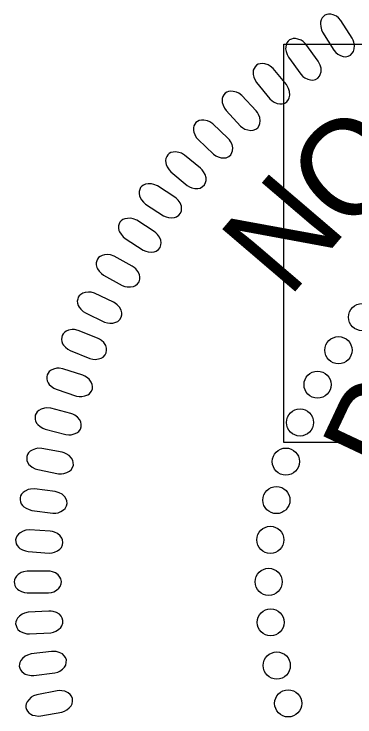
# Model space of a CAD drawing. Extents: x 505602 to 507286, y 483109 to 489436.
# Drawn here: x 507079.65 to 507099.79, y 484086.3 to 484127.78 of the extents above; entities that cross this region are included whole.
import ezdxf

# ---------------------------------------------------------------- set-up
doc = ezdxf.new("R2010")
doc.units = 0
doc.layers.add('Sheet PE Seal Cell', color=7, linetype='Continuous')
doc.layers.add('Sheet Sticker Incomplete CELL', color=7, linetype='Continuous')

msp = doc.modelspace()

# ---------------------------------------------------------------- linework, layer by layer
at = {"layer": 'Sheet PE Seal Cell'}
for points in [[(507099.622, 484126.354), (507098.965, 484127.39), (507098.816, 484127.556), (507098.698, 484127.645), (507098.512, 484127.729), (507098.371, 484127.769), (507098.234, 484127.776), (507098.124, 484127.754), (507098.019, 484127.711), (507097.934, 484127.634), (507097.85, 484127.545), (507097.793, 484127.438), (507097.758, 484127.298), (507097.751, 484127.198), (507097.774, 484127.036), (507097.82, 484126.852), (507097.886, 484126.705), (507098.553, 484125.64), (507098.662, 484125.509), (507098.775, 484125.415), (507098.937, 484125.329), (507099.106, 484125.271), (507099.23, 484125.255), (507099.395, 484125.289), (507099.532, 484125.352), (507099.637, 484125.466), (507099.699, 484125.564), (507099.753, 484125.716), (507099.763, 484125.924), (507099.723, 484126.111), (507099.679, 484126.236)], [(507097.622, 484124.999), (507096.901, 484125.992), (507096.742, 484126.148), (507096.618, 484126.23), (507096.427, 484126.302), (507096.284, 484126.333), (507096.147, 484126.331), (507096.038, 484126.303), (507095.936, 484126.253), (507095.857, 484126.171), (507095.778, 484126.076), (507095.728, 484125.967), (507095.702, 484125.824), (507095.7, 484125.725), (507095.734, 484125.563), (507095.791, 484125.383), (507095.867, 484125.241), (507096.599, 484124.22), (507096.717, 484124.096), (507096.835, 484124.009), (507097.001, 484123.932), (507097.174, 484123.886), (507097.3, 484123.878), (507097.462, 484123.922), (507097.594, 484123.994), (507097.692, 484124.114), (507097.747, 484124.215), (507097.792, 484124.371), (507097.789, 484124.579), (507097.738, 484124.763), (507097.686, 484124.886)], [(507095.741, 484123.61), (507094.959, 484124.556), (507094.791, 484124.701), (507094.662, 484124.776), (507094.468, 484124.835), (507094.323, 484124.858), (507094.185, 484124.848), (507094.08, 484124.811), (507093.98, 484124.755), (507093.906, 484124.668), (507093.834, 484124.569), (507093.79, 484124.457), (507093.774, 484124.312), (507093.778, 484124.213), (507093.822, 484124.055), (507093.89, 484123.878), (507093.975, 484123.741), (507094.769, 484122.768), (507094.895, 484122.651), (507095.018, 484122.573), (507095.189, 484122.507), (507095.364, 484122.471), (507095.49, 484122.471), (507095.649, 484122.525), (507095.777, 484122.605), (507095.867, 484122.731), (507095.916, 484122.836), (507095.95, 484122.994), (507095.934, 484123.2), (507095.872, 484123.382), (507095.812, 484123.501)], [(507093.954, 484122.071), (507093.114, 484122.966), (507092.937, 484123.101), (507092.803, 484123.167), (507092.605, 484123.214), (507092.46, 484123.227), (507092.323, 484123.209), (507092.219, 484123.166), (507092.124, 484123.104), (507092.056, 484123.012), (507091.989, 484122.908), (507091.954, 484122.794), (507091.946, 484122.649), (507091.956, 484122.55), (507092.01, 484122.395), (507092.089, 484122.223), (507092.181, 484122.092), (507093.037, 484121.17), (507093.169, 484121.061), (507093.297, 484120.991), (507093.472, 484120.936), (507093.65, 484120.91), (507093.775, 484120.918), (507093.93, 484120.982), (507094.053, 484121.071), (507094.134, 484121.202), (507094.177, 484121.31), (507094.201, 484121.469), (507094.173, 484121.674), (507094.098, 484121.852), (507094.032, 484121.967)], [(507092.291, 484120.462), (507091.398, 484121.302), (507091.212, 484121.425), (507091.074, 484121.483), (507090.874, 484121.517), (507090.728, 484121.522), (507090.592, 484121.494), (507090.492, 484121.445), (507090.401, 484121.377), (507090.339, 484121.282), (507090.278, 484121.174), (507090.25, 484121.057), (507090.251, 484120.913), (507090.268, 484120.814), (507090.331, 484120.662), (507090.421, 484120.496), (507090.522, 484120.37), (507091.433, 484119.504), (507091.571, 484119.405), (507091.704, 484119.342), (507091.882, 484119.298), (507092.06, 484119.284), (507092.185, 484119.3), (507092.336, 484119.374), (507092.453, 484119.469), (507092.526, 484119.605), (507092.561, 484119.715), (507092.576, 484119.877), (507092.534, 484120.08), (507092.45, 484120.252), (507092.376, 484120.362)], [(507090.678, 484118.675), (507089.733, 484119.458), (507089.54, 484119.568), (507089.399, 484119.617), (507089.197, 484119.639), (507089.051, 484119.634), (507088.918, 484119.599), (507088.821, 484119.544), (507088.734, 484119.47), (507088.677, 484119.371), (507088.625, 484119.259), (507088.603, 484119.141), (507088.614, 484118.997), (507088.637, 484118.9), (507088.709, 484118.752), (507088.81, 484118.591), (507088.918, 484118.473), (507089.881, 484117.666), (507090.026, 484117.575), (507090.162, 484117.521), (507090.343, 484117.488), (507090.521, 484117.485), (507090.645, 484117.51), (507090.791, 484117.592), (507090.901, 484117.694), (507090.966, 484117.835), (507090.995, 484117.947), (507090.999, 484118.109), (507090.945, 484118.309), (507090.849, 484118.475), (507090.768, 484118.581)], [(507089.153, 484116.973), (507088.123, 484117.639), (507087.918, 484117.726), (507087.773, 484117.758), (507087.57, 484117.756), (507087.425, 484117.734), (507087.297, 484117.683), (507087.207, 484117.617), (507087.129, 484117.533), (507087.085, 484117.429), (507087.046, 484117.312), (507087.038, 484117.192), (507087.066, 484117.05), (507087.1, 484116.956), (507087.189, 484116.818), (507087.308, 484116.67), (507087.429, 484116.565), (507088.481, 484115.877), (507088.635, 484115.803), (507088.777, 484115.766), (507088.96, 484115.754), (507089.138, 484115.773), (507089.258, 484115.812), (507089.393, 484115.911), (507089.491, 484116.025), (507089.538, 484116.172), (507089.553, 484116.287), (507089.539, 484116.448), (507089.461, 484116.64), (507089.347, 484116.795), (507089.254, 484116.89)], [(507087.939, 484114.95), (507086.904, 484115.608), (507086.699, 484115.694), (507086.553, 484115.725), (507086.349, 484115.721), (507086.204, 484115.698), (507086.077, 484115.646), (507085.987, 484115.579), (507085.91, 484115.495), (507085.867, 484115.389), (507085.828, 484115.273), (507085.822, 484115.152), (507085.851, 484115.01), (507085.886, 484114.917), (507085.976, 484114.78), (507086.095, 484114.633), (507086.218, 484114.529), (507087.275, 484113.849), (507087.43, 484113.777), (507087.572, 484113.74), (507087.755, 484113.73), (507087.933, 484113.75), (507088.052, 484113.789), (507088.187, 484113.89), (507088.284, 484114.005), (507088.33, 484114.152), (507088.344, 484114.268), (507088.328, 484114.429), (507088.25, 484114.62), (507088.134, 484114.773), (507088.04, 484114.868)], [(507086.636, 484112.901), (507085.561, 484113.493), (507085.351, 484113.565), (507085.203, 484113.587), (507085, 484113.571), (507084.857, 484113.538), (507084.733, 484113.479), (507084.648, 484113.406), (507084.576, 484113.318), (507084.54, 484113.209), (507084.509, 484113.09), (507084.51, 484112.97), (507084.548, 484112.83), (507084.589, 484112.739), (507084.687, 484112.608), (507084.816, 484112.469), (507084.945, 484112.372), (507086.042, 484111.76), (507086.201, 484111.698), (507086.345, 484111.671), (507086.528, 484111.672), (507086.705, 484111.703), (507086.822, 484111.75), (507086.95, 484111.858), (507087.039, 484111.98), (507087.076, 484112.13), (507087.083, 484112.245), (507087.057, 484112.405), (507086.966, 484112.591), (507086.841, 484112.737), (507086.742, 484112.826)], [(507085.527, 484110.777), (507084.417, 484111.3), (507084.203, 484111.36), (507084.054, 484111.372), (507083.853, 484111.343), (507083.712, 484111.301), (507083.592, 484111.234), (507083.511, 484111.156), (507083.446, 484111.063), (507083.416, 484110.953), (507083.392, 484110.832), (507083.401, 484110.713), (507083.447, 484110.575), (507083.494, 484110.487), (507083.601, 484110.363), (507083.738, 484110.232), (507083.872, 484110.143), (507085.007, 484109.601), (507085.169, 484109.55), (507085.314, 484109.531), (507085.497, 484109.544), (507085.671, 484109.586), (507085.784, 484109.639), (507085.906, 484109.756), (507085.988, 484109.883), (507086.015, 484110.035), (507086.014, 484110.151), (507085.978, 484110.308), (507085.876, 484110.489), (507085.742, 484110.626), (507085.637, 484110.709)], [(507084.587, 484108.659), (507083.447, 484109.11), (507083.229, 484109.156), (507083.08, 484109.16), (507082.881, 484109.118), (507082.743, 484109.068), (507082.628, 484108.993), (507082.553, 484108.91), (507082.492, 484108.813), (507082.47, 484108.702), (507082.454, 484108.579), (507082.47, 484108.46), (507082.525, 484108.326), (507082.577, 484108.241), (507082.691, 484108.123), (507082.836, 484108.002), (507082.976, 484107.922), (507084.141, 484107.452), (507084.307, 484107.411), (507084.454, 484107.401), (507084.635, 484107.425), (507084.806, 484107.478), (507084.916, 484107.539), (507085.03, 484107.663), (507085.103, 484107.794), (507085.121, 484107.948), (507085.113, 484108.064), (507085.068, 484108.219), (507084.954, 484108.392), (507084.812, 484108.521), (507084.702, 484108.597)], [(507083.712, 484106.469), (507082.545, 484106.848), (507082.325, 484106.88), (507082.176, 484106.875), (507081.98, 484106.82), (507081.845, 484106.761), (507081.735, 484106.679), (507081.665, 484106.593), (507081.611, 484106.492), (507081.596, 484106.379), (507081.587, 484106.256), (507081.611, 484106.139), (507081.674, 484106.008), (507081.732, 484105.926), (507081.853, 484105.816), (507082.005, 484105.704), (507082.15, 484105.633), (507083.342, 484105.237), (507083.51, 484105.206), (507083.657, 484105.206), (507083.837, 484105.242), (507084.004, 484105.305), (507084.111, 484105.373), (507084.216, 484105.503), (507084.281, 484105.639), (507084.289, 484105.794), (507084.274, 484105.909), (507084.219, 484106.061), (507084.094, 484106.227), (507083.944, 484106.346), (507083.83, 484106.415)], [(507083.007, 484104.214), (507081.819, 484104.519), (507081.598, 484104.537), (507081.449, 484104.522), (507081.257, 484104.455), (507081.126, 484104.389), (507081.021, 484104.3), (507080.957, 484104.208), (507080.909, 484104.104), (507080.9, 484103.992), (507080.9, 484103.868), (507080.931, 484103.751), (507081.002, 484103.626), (507081.064, 484103.548), (507081.193, 484103.445), (507081.352, 484103.343), (507081.501, 484103.281), (507082.716, 484102.961), (507082.886, 484102.94), (507083.032, 484102.949), (507083.209, 484102.997), (507083.372, 484103.07), (507083.474, 484103.144), (507083.571, 484103.282), (507083.627, 484103.421), (507083.626, 484103.576), (507083.603, 484103.69), (507083.539, 484103.838), (507083.404, 484103.996), (507083.247, 484104.106), (507083.128, 484104.166)], [(507082.496, 484101.918), (507081.291, 484102.148), (507081.069, 484102.153), (507080.921, 484102.128), (507080.734, 484102.049), (507080.608, 484101.975), (507080.508, 484101.879), (507080.45, 484101.784), (507080.409, 484101.678), (507080.408, 484101.564), (507080.415, 484101.441), (507080.453, 484101.327), (507080.532, 484101.205), (507080.599, 484101.131), (507080.733, 484101.037), (507080.899, 484100.945), (507081.051, 484100.893), (507082.284, 484100.649), (507082.455, 484100.64), (507082.601, 484100.658), (507082.774, 484100.716), (507082.932, 484100.8), (507083.029, 484100.88), (507083.117, 484101.023), (507083.165, 484101.166), (507083.154, 484101.321), (507083.124, 484101.433), (507083.05, 484101.576), (507082.906, 484101.726), (507082.742, 484101.826), (507082.62, 484101.879)], [(507082.076, 484099.603), (507080.859, 484099.757), (507080.636, 484099.748), (507080.491, 484099.714), (507080.309, 484099.624), (507080.187, 484099.542), (507080.094, 484099.44), (507080.042, 484099.341), (507080.008, 484099.232), (507080.014, 484099.119), (507080.028, 484098.996), (507080.074, 484098.885), (507080.161, 484098.769), (507080.232, 484098.7), (507080.372, 484098.614), (507080.542, 484098.532), (507080.698, 484098.49), (507081.944, 484098.324), (507082.115, 484098.326), (507082.259, 484098.353), (507082.428, 484098.421), (507082.581, 484098.515), (507082.672, 484098.602), (507082.752, 484098.75), (507082.79, 484098.896), (507082.769, 484099.049), (507082.733, 484099.159), (507082.65, 484099.298), (507082.497, 484099.437), (507082.327, 484099.527), (507082.202, 484099.572)], [(507081.789, 484097.26), (507080.565, 484097.337), (507080.343, 484097.314), (507080.2, 484097.27), (507080.024, 484097.169), (507079.908, 484097.079), (507079.822, 484096.972), (507079.776, 484096.87), (507079.749, 484096.759), (507079.762, 484096.647), (507079.784, 484096.525), (507079.837, 484096.417), (507079.93, 484096.306), (507080.006, 484096.242), (507080.151, 484096.165), (507080.326, 484096.094), (507080.484, 484096.061), (507081.738, 484095.974), (507081.908, 484095.986), (507082.05, 484096.022), (507082.215, 484096.102), (507082.362, 484096.205), (507082.448, 484096.297), (507082.517, 484096.45), (507082.546, 484096.598), (507082.516, 484096.749), (507082.473, 484096.857), (507082.382, 484096.99), (507082.22, 484097.12), (507082.045, 484097.199), (507081.917, 484097.236)], [(507081.659, 484094.909), (507080.432, 484094.909), (507080.213, 484094.871), (507080.073, 484094.82), (507079.904, 484094.708), (507079.794, 484094.61), (507079.714, 484094.498), (507079.674, 484094.394), (507079.654, 484094.281), (507079.674, 484094.17), (507079.704, 484094.05), (507079.763, 484093.945), (507079.864, 484093.84), (507079.943, 484093.781), (507080.093, 484093.713), (507080.273, 484093.653), (507080.432, 484093.631), (507081.689, 484093.623), (507081.858, 484093.645), (507081.998, 484093.69), (507082.157, 484093.78), (507082.297, 484093.892), (507082.377, 484093.989), (507082.437, 484094.146), (507082.457, 484094.296), (507082.416, 484094.445), (507082.367, 484094.549), (507082.268, 484094.677), (507082.098, 484094.797), (507081.918, 484094.864), (507081.789, 484094.894)], [(507081.712, 484092.551), (507080.487, 484092.475), (507080.271, 484092.424), (507080.134, 484092.363), (507079.972, 484092.24), (507079.868, 484092.136), (507079.796, 484092.019), (507079.763, 484091.913), (507079.75, 484091.799), (507079.777, 484091.689), (507079.815, 484091.571), (507079.88, 484091.47), (507079.987, 484091.372), (507080.07, 484091.318), (507080.223, 484091.26), (507080.406, 484091.211), (507080.566, 484091.199), (507081.822, 484091.27), (507081.99, 484091.303), (507082.126, 484091.357), (507082.279, 484091.456), (507082.412, 484091.577), (507082.486, 484091.678), (507082.536, 484091.839), (507082.546, 484091.989), (507082.497, 484092.136), (507082.44, 484092.238), (507082.333, 484092.358), (507082.157, 484092.467), (507081.973, 484092.523), (507081.842, 484092.545)], [(507081.876, 484090.17), (507080.659, 484090.017), (507080.446, 484089.952), (507080.314, 484089.883), (507080.16, 484089.75), (507080.063, 484089.64), (507079.998, 484089.519), (507079.972, 484089.41), (507079.966, 484089.296), (507080, 484089.188), (507080.044, 484089.073), (507080.116, 484088.976), (507080.229, 484088.885), (507080.316, 484088.835), (507080.472, 484088.788), (507080.658, 484088.751), (507080.819, 484088.748), (507082.067, 484088.898), (507082.232, 484088.941), (507082.365, 484089.004), (507082.512, 484089.112), (507082.636, 484089.241), (507082.704, 484089.347), (507082.743, 484089.511), (507082.744, 484089.662), (507082.686, 484089.805), (507082.623, 484089.903), (507082.509, 484090.017), (507082.326, 484090.113), (507082.139, 484090.158), (507082.007, 484090.171)], [(507082.21, 484087.845), (507081.004, 484087.615), (507080.796, 484087.537), (507080.669, 484087.461), (507080.523, 484087.318), (507080.433, 484087.202), (507080.376, 484087.077), (507080.356, 484086.967), (507080.358, 484086.853), (507080.398, 484086.747), (507080.45, 484086.635), (507080.528, 484086.543), (507080.646, 484086.459), (507080.735, 484086.415), (507080.895, 484086.377), (507081.083, 484086.352), (507081.243, 484086.359), (507082.479, 484086.587), (507082.642, 484086.641), (507082.771, 484086.711), (507082.91, 484086.829), (507083.027, 484086.966), (507083.087, 484087.076), (507083.116, 484087.241), (507083.108, 484087.392), (507083.041, 484087.531), (507082.972, 484087.625), (507082.85, 484087.731), (507082.662, 484087.816), (507082.472, 484087.849), (507082.34, 484087.854)]]:
    msp.add_lwpolyline(points, close=True, dxfattribs=at)
for centre in [(507100.214, 484109.892), (507098.82, 484107.941), (507097.585, 484105.909), (507096.549, 484103.679), (507095.712, 484101.368), (507095.154, 484099.098), (507094.795, 484096.748), (507094.698, 484094.273), (507094.817, 484091.883), (507095.174, 484089.333), (507095.85, 484087.102)]:
    msp.add_circle(centre, 0.801, dxfattribs=at)
at = {"layer": 'Sheet Sticker Incomplete CELL'}
msp.add_lwpolyline([(507095.597, 484102.505), (507095.597, 484126.005), (507242.597, 484126.005), (507242.597, 484102.505)], close=True, dxfattribs=at)

# ---------------------------------------------------------------- texts
at = {"layer": 'Sheet PE Seal Cell'}
for s, rotation, p in [('O', 43.0132, (507099.209, 484114.686)), ('N', 49.5025, (507095.863, 484110.931)), ('P', 64.8074, (507102.793, 484099.888))]:
    msp.add_text(s, height=5.669, rotation=rotation, dxfattribs=at).set_placement(p)

doc.saveas('drawing.dxf')
